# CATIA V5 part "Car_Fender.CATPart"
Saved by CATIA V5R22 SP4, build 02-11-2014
Part number: Car_Fender
Material "ｱﾙﾐﾆｳﾑ": density 2710 kg/m3, Young's modulus 7e+10 Pa, Poisson ratio 0.346, thermal expansion 2.36e-05 1/K
Bounding box of the stored display mesh (mm): x -800 to 0, y -40 to 122.298, z 0 to 580
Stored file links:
  C:\DATA\Car_ASSY\教育モデル\5_ASM\FIN\Car_Fender.CATPart
  C:\DATA\Car_ASSY\Car_Fender.CATPart
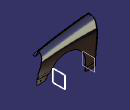
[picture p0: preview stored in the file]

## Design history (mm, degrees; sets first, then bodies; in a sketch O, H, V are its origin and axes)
Set1
  Plane1: type Offset, RefPlane yz-plane, Offset 400, reversed
  Plane2: type Offset, RefPlane Plane1, Offset 400, reversed
  Plane3: type Offset, RefPlane yz-plane, Offset 390, reversed
Body1 (main body)
  Body2
    Sketch1 on yz-plane, origin (0, 0, 0), H (0, 1, 0), V (0, 0, 1)
      point P4 (100, 50)
      point P5 (10, 450)
      spline S1 through (10, 450) (100, 50)
      line L1 (0, 450) -> (10, 450)
      line L2 (0, 0) -> (0, 450)
      line L3 (100, 0) -> (0, 0)
      line L4 (100, 50) -> (100, 0)
      point P6 (100, 50)
      point P7 (10, 450)
      distance P4 L3 = 50
      distance P5 L2 = 10
      distance L4 L2 = 100
      distance L1 H = 450
      coincidence: L2 V, H L3, P4 P6, P7 P5
    Sketch2 on Plane1, origin (-400, 0, 0), H (0, 1, 0), V (0, 0, 1)
      point P4 (100, 50)
      point P5 (10, 530)
      spline S1 through (10, 530) (100, 50)
      line L1 (0, 530) -> (10, 530)
      line L2 (0, 0) -> (0, 530)
      line L3 (100, 0) -> (0, 0)
      line L4 (100, 50) -> (100, 0)
      point P6 (100, 50)
      point P7 (10, 530)
      distance P4 L3 = 50
      distance P5 L2 = 10
      distance L4 L2 = 100
      distance L1 H = 530
      coincidence: L2 V, H L3, P4 P6, P7 P5
    Sketch3 on Plane2, origin (-800, 0, 0), H (0, 1, 0), V (0, 0, 1)
      point P4 (100, 50)
      point P5 (10, 580)
      spline S1 through (10, 580) (100, 50)
      line L1 (0, 580) -> (10, 580)
      line L2 (0, 0) -> (0, 580)
      line L3 (100, 0) -> (0, 0)
      line L4 (100, 50) -> (100, 0)
      point P6 (100, 50)
      point P7 (10, 580)
      distance P4 L3 = 50
      distance P5 L2 = 10
      distance L4 L2 = 100
      distance L1 H = 580
      coincidence: L2 V, H L3, P4 P6, P7 P5
    Loft1: solid, Sections (Sketch1; Sketch2; Sketch3)
    Body3
      Sketch4 on zx-plane, origin (0, 0, 0), H (-1, 0, 0), V (0, 0, 1)
        line L1 (-46.4952, 240) -> (159.0779, 240)
        arc A1 centre (390, 110) radius 265 from (159.0779, 240) to (655, 109.9999) cw
        point P2 (390, 110)
        line L2 (655, 109.9999) -> (655, -30)
        line L3 (-46.4952, 626.6258) -> (850, 626.6258)
        line L4 (850, 626.6258) -> (850, -30)
        line L5 (850, -30) -> (655, -30)
        line L6 (-46.4952, 626.6258) -> (-46.4952, 240)
        radius A1 = 265
        distance P2 H = 110
        distance V P2 = 390
        distance H L1 = 240
        horizontal: L1 H, L3 H, L5 H
        tangency: L2 A1
        vertical: L2 V, L4 V, L6 V
      Pad1: profile Sketch4, direction (0, 1, 0), length 340, mirrored extent
    Intersect1: tool Body3
    Shell1: ExtOffset 0, Face (face of Loft1; face of Pad1 from Sketch4.A1; face of Pad1 from Sketch4.L1; face of Loft1; face of Loft1; face of Loft1), IntOffset 3
    Sketch5 on Plane2, origin (-800, 0, 0), H (0, 1, 0), V (0, 0, 1)
      line L1 (0, 580) -> (0, 545)
      line L2 (-5, 540) -> (-40, 540)
      point P2 (-40, 540)
      reference projected line E1 (10, 580) -> (0, 580)
      reference intersected line E2 (0, 0) -> (0, 580)
      arc A1 centre (-5, 545) radius 5 from (-5, 540) to (0, 545) ccw
      line L3 (-5, 537) -> (-40, 537)
      arc A2 centre (-5, 545) radius 8 from (-5, 537) to (3, 545) ccw
      line L4 (3, 580) -> (3, 545)
      line L5 (-40, 537) -> (-40, 540)
      line L6 (3, 580) -> (0, 580)
      reference projected line E3 (10, 580) -> (0, 580)
      distance E1 L2 = 40
      radius A1 = 5
      distance L1 P2 = 40
      length L5 = 3
      length L6 = 3
      radius A2 = 8
      vertical: L1 V, L4 V, L5 V
      horizontal: L2 H, L6 H, L3 H
      coincidence: L1 E2, L6 E3
      tangency: A1 L2, A1 L1, L4 A2, A2 L3
    Rib1: profile Sketch5, centre curve edge [face of Loft1 | face of Loft1]
    Sketch6 on Plane2, origin (-800, 0, 0), H (0, 1, 0), V (0, 0, 1)
      projected curve E1 from edge [face of Shell1 | face of Rib1]
      projected line E2 (10, 576.9862) -> (3, 576.9862) from edge [face of Shell1 | face of Rib1]
      point P4 (3, 576.9862)
      projected line E3 (3, 576.9862) -> (3, 545) from edge [face of Rib1 | face of Rib1]
      projected line E4 (3, 576.9862) -> (3, 399.233) from edge [face of Rib1 | face of Rib1]
      point P5 (3, 576.9862)
      projected line E5 (97, 0) -> (97, 50) from edge [face of Shell1 | face of Rib1]
      line L1 (97, 0) -> (37, 0)
      line L2 (37, 0) -> (17.9077, 155.4943)
      arc A1 centre (2003, 399.233) radius 2000 from (3, 399.233) to (17.9077, 155.4943) ccw
      angle L1 L2 = 97
      length L1 = 60
      radius A1 = 2000
      horizontal: L1 H
      tangency: A1 E3, A1 L2
      coincidence: P4 P5
    Pad2: profile Sketch6, direction (1, 0, 0), length 10, opposite side length -7
    Sketch7 on yz-plane, origin (0, 0, 0), H (0, 1, 0), V (0, 0, 1)
      projected curve E1 from edge [face of Loft1 | face of Shell1]
      projected curve E2 from edge [face of Loft1 | face of Shell1]
      point P1 (103.8705, 240)
      line L1 (100.927, 243) -> (92.1161, 243)
      line L2 (86.1161, 237) -> (86.1161, 160)
      line L3 (86.1161, 160) -> (89.1161, 160)
      line L4 (89.1161, 160) -> (89.1161, 237)
      point P5 (103.8705, 240)
      line L5 (101.1067, 267.4285) -> (104.1068, 267.4285)
      point P6 (101.1068, 267.4285)
      point P7 (104.1068, 267.4285)
      offset curve E3 from edge [face of Loft1 | face of Shell1]
      offset curve E4 from edge [face of Loft1 | face of Shell1]
      line L6 (92.1161, 240) -> (103.8705, 240)
      arc A1 centre (92.1161, 237) radius 3 from (92.1161, 240) to (89.1161, 237) ccw
      arc A2 centre (92.1161, 237) radius 6 from (92.1161, 243) to (86.1161, 237) ccw
      distance L4 L2 = 3
      distance P6 P7 = 3
      distance L4 E1 = 15
      distance L1 L6 = 3
      radius A1 = 3
      radius A2 = 6
      distance L6 L3 = 80
      horizontal: L1 H, L3 H, L5 H, L6 H
      vertical: L2 V, L4 V
      coincidence: P7 E1, E3 P6, P6 L5, P7 L5, P5 P1
      tangency: A1 L6, A1 L4, A2 L1, A2 L2
    Rib2: profile Sketch7, centre curve edge [face of Pad1 from Sketch4.L1 | face of Shell1]
    Body4
      Sketch8 on zx-plane, origin (0, 0, 0), H (-1, 0, 0), V (0, 0, 1)
        point P1 (0, 300)
        line L1 (0, 300) -> (127.0171, 520)
        line L2 (127.0171, 520) -> (-100, 520)
        line L3 (-100, 520) -> (-100, 300)
        line L4 (-100, 300) -> (0, 300)
        angle L1 L4 = 120
        distance L4 H = 300
        coincidence: P1 V
        horizontal: L2 H, L4 H
        vertical: L3 V
      Pad3: profile Sketch8, direction (0, 1, 0), length 220, mirrored extent
    Remove1: tool Body4
    Sketch9 on xy-plane, origin (0, 0, 0), H (1, 0, 0), V (0, 1, 0)
      line L1 (-730, -50.1266) -> (-730, -25)
      arc A1 centre (-725, -25) radius 5 from (-730, -25) to (-720, -25) cw
      point P3 (-725, -25)
      line L2 (-720, -25) -> (-720, -50.1266)
      line L3 (-720, -50.1266) -> (-730, -50.1266)
      reference projected line E1 (-5.7993, -40) -> (-800, -40) from edge [face of Rib1 | face of Rib1]
      reference projected line E2 (-800, -40) -> (-800, -5) from edge [face of Rib1 | face of Rib1]
      radius A1 = 5
      distance P3 E1 = 15
      distance P3 E2 = 75
      vertical: L1 V, L2 V
      tangency: A1 L1, L2 A1
      horizontal: L3 H
    Pocket1: profile Sketch9, direction (0, 0, 1), length 660
    RectPattern1: of Pocket1, direction 1 instances 3, spacing 270, along X axis
    Sketch10 on {plane type Tangent, Support face of Rib2, RefPoint {point type OnSurface, Support face of Rib2, RefPoint {point stored without definition}, Length 0, Direction (0, 0, -1000)}}, origin (-99.3533, 90.7181, 174.1703), H (0.9999, -0.0138, 0), V (0, 0, 1)
      point P1 (49.366, 15.8297)
      reference projected line E1 (99.366, -14.1703) -> (99.366, 62.8297) from edge [face of Rib2 | face of Rib2]
      reference projected line E2 (-59.6229, -14.1703) -> (99.366, -14.1703) from edge [face of Rib2 | face of Rib2]
      distance P1 E1 = 50
      distance P1 E2 = 30
    Hole1: placed by Sketch10, at (-49.9929, 89.9835, 190) direction (-0.016, -0.9999, 0), diameter 15, depth 15
    Chamfer1: length 70, angle 35, on edge [face of Rib2 | face of Rib2]
    Fillet1: radius 10, on edge [face of Rib1 | face of Rib1]; edge [face of Rib1 | face of Pad3 from Sketch8.L1]
    Fillet2: radius 5, on edge [face of Rib2 | face of Chamfer1]; edge [face of Chamfer1 | face of Rib2]; edge [face of Rib2 | face of Rib2]
    Fillet3: radius 10, on edge [face of Pad1 from Sketch4.L2 | face of Pad2]
  Add1: tool Body2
